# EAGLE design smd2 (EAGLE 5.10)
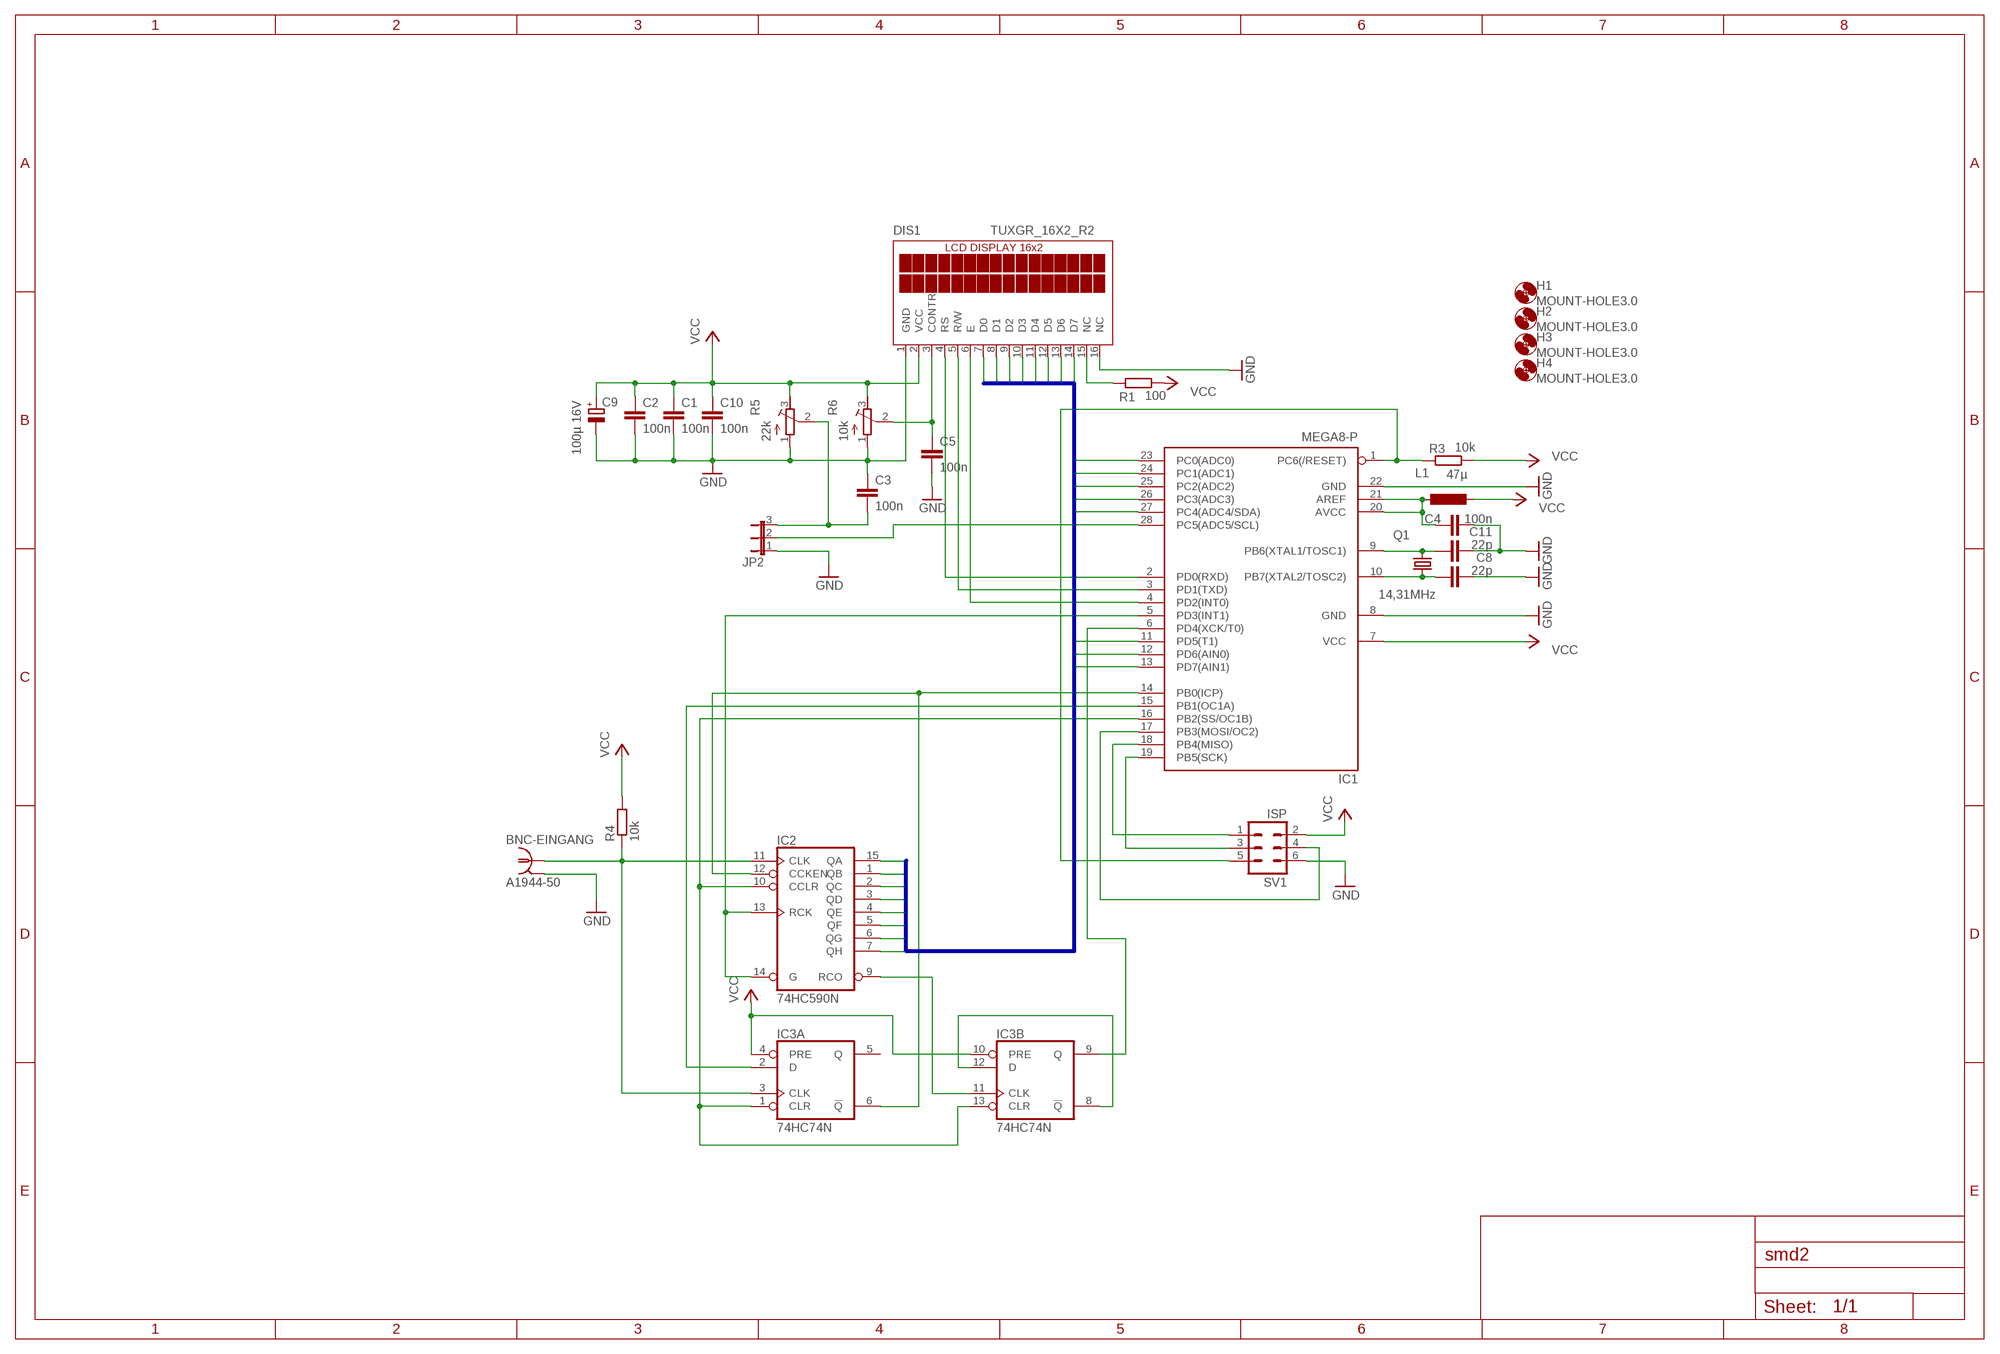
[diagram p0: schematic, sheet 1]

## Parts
BNC-EINGANG  A1944-50  [A1944]
C1  100n  C-EUC1206K  [C1206K]
C2  100n  C-EUC1206K  [C1206K]
C3  100n  C-EUC1206K  [C1206K]
C4  100n  C-EUC1206K  [C1206K]
C5  100n  C-EUC1206K  [C1206K]
C8  22p  C-EUC1206K  [C1206K]
C9  100µ 16V  CPOL-EUE5-8.5  [E5-8,5]
C10  100n  C-EUC1206K  [C1206K]
C11  22p  C-EUC1206K  [C1206K]
DIS1  TUXGR_16X2_R2  [TUXGR_16X2_R2]
H1  MOUNT-HOLE3.0  [3,0]
H2  MOUNT-HOLE3.0  [3,0]
H3  MOUNT-HOLE3.0  [3,0]
H4  MOUNT-HOLE3.0  [3,0]
IC1  MEGA8-P  [DIL28-3]
IC2  74HC590N  [DIL16]
IC3  74HC74N  [DIL14]
JP2  JP2E  [JP2]
L1  47µ  L-EU0204/7  [0204/7]
Q1  14,31MHz  CRYSTALHC49S  [HC49/S]
R1  100  R-EU_0204/7  [0204/7]
R3  10k  R-EU_0204/7  [0204/7]
R4  10k  R-EU_0204/7  [0204/7]
R5  22k  R-TRIMM3296Y  [RTRIM3296Y]
R6  10k  R-TRIMM3296Y  [RTRIM3296Y]
SV1  ISP  ML6  [ML6]

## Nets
0: DIS1.7(D0) IC1.23(PC0(ADC0)) IC2.15(QA)
1: DIS1.8(D1) IC1.24(PC1(ADC1)) IC2.1(QB)
2: DIS1.9(D2) IC1.25(PC2(ADC2)) IC2.2(QC)
3: DIS1.10(D3) IC1.26(PC3(ADC3)) IC2.3(QD)
4: DIS1.11(D4) IC1.27(PC4(ADC4/SDA)) IC2.4(QE)
5: DIS1.12(D5) IC1.11(PD5(T1)) IC2.5(QF)
6: DIS1.13(D6) IC1.12(PD6(AIN0)) IC2.6(QG)
7: DIS1.14(D7) IC1.13(PD7(AIN1)) IC2.7(QH)
GND: BNC-EINGANG.2(GND) C1.2 C2.2 C3.1 C4.2 C5.2 C8.2 C9.- C10.2 C11.2 DIS1.1(GND) DIS1.16(NC) IC1.8(GND) IC1.22(GND) JP2.1 R5.1(E) R6.1(E) SV1.6
N$1: BNC-EINGANG.1 IC2.11(CLK) IC3.3(A:CLK) R4.1
N$2: DIS1.6(E) IC1.4(PD2(INT0))
N$3: DIS1.5(R/W) IC1.3(PD1(TXD))
N$4: DIS1.4(RS) IC1.2(PD0(RXD))
N$5: C5.1 DIS1.3(CONTR) R6.2(S)
N$6: IC1.5(PD3(INT1)) IC2.13(RCK) IC2.14(G)
N$7: IC1.14(PB0(ICP)) IC2.12(CCKEN) IC3.6(A:!Q)
N$8: IC1.16(PB2(SS/OC1B)) IC2.10(CCLR) IC3.1(A:CLR) IC3.13(B:CLR)
N$9: IC2.9(RCO) IC3.11(B:CLK)
N$10: IC1.15(PB1(OC1A)) IC3.2(A:D)
N$11: IC3.8(B:!Q) IC3.12(B:D)
N$12: IC1.6(PD4(XCK/T0)) IC3.9(B:Q)
N$13: IC1.19(PB5(SCK)) SV1.3
N$14: IC1.18(PB4(MISO)) SV1.1
N$15: IC1.17(PB3(MOSI/OC2)) SV1.4
N$16: IC1.1(PC6(/RESET)) R3.1 SV1.5
N$17: C3.2 JP2.3 R5.2(S)
N$18: C4.1 IC1.20(AVCC) IC1.21(AREF) L1.1
N$19: C11.1 IC1.9(PB6(XTAL1/TOSC1)) Q1.2
N$20: C8.1 IC1.10(PB7(XTAL2/TOSC2)) Q1.1
N$21: DIS1.15(NC) R1.1
N$22: IC1.28(PC5(ADC5/SCL)) JP2.2
VCC: C1.1 C2.1 C9.+ C10.1 DIS1.2(VCC) IC1.7(VCC) IC3.4(A:PRE) IC3.10(B:PRE) L1.2 R1.2 R3.2 R4.2 R5.3(A) R6.3(A) SV1.2
Unconnected: IC3.5(A:Q)

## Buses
B$1

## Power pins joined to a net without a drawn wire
GND: BNC-EINGANG.3(GND) BNC-EINGANG.4(GND) BNC-EINGANG.5(GND) IC2.8(GND) IC3.7(P:GND)
VCC: IC2.16(VCC) IC3.14(P:VCC)

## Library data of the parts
BNC-EINGANG = con-coax:A1944-50: BNC CONNECTOR 50 Ohm distributor Buerklin 78F2475
C1-C5 C8 C10 C11 = rcl:C-EU: CAPACITOR, European symbol
C9 = rcl:CPOL-EU: POLARIZED CAPACITOR, European symbol
DIS1 = display-lcd:TUXGR_16X2_R2: Tuxgraphics LCD display 16x2 characters reflective, without background light Source: tuxgr_12x2_r2.pdf
H1-H4 = holes:MOUNT-HOLE: MOUNTING HOLE with drill center marker
IC1 = atmel:MEGA8-P: MICROCONTROLLER 8 Kbytes FLASH, 1 kbytes SRAM, 512 bytes EEPROM, USART, 4-channel 10 bit ADC, 2-channel 8 bit ADC Pin compatible with Atmega48, ATMega88, ATMega168 Source: avr.lbr
IC2 = 74xx-eu:74*590: 8-bit binary COUNTER, output register
IC3 = 74xx-eu:74*74: Dual D type positive edge triggered FLIP FLOP, preset and clear
JP2 = jumper:JP2E: JUMPER
L1 = rcl:L-EU: INDUCTOR, European symbol
Q1 = crystal:CRYSTAL: CRYSTAL
R1 R3 R4 = rcl:R-EU_: RESISTOR, European symbol
R5 R6 = rcl:R-TRIMM: Trimm resistor
SV1 = con-harting-ml:ML6: HARTING

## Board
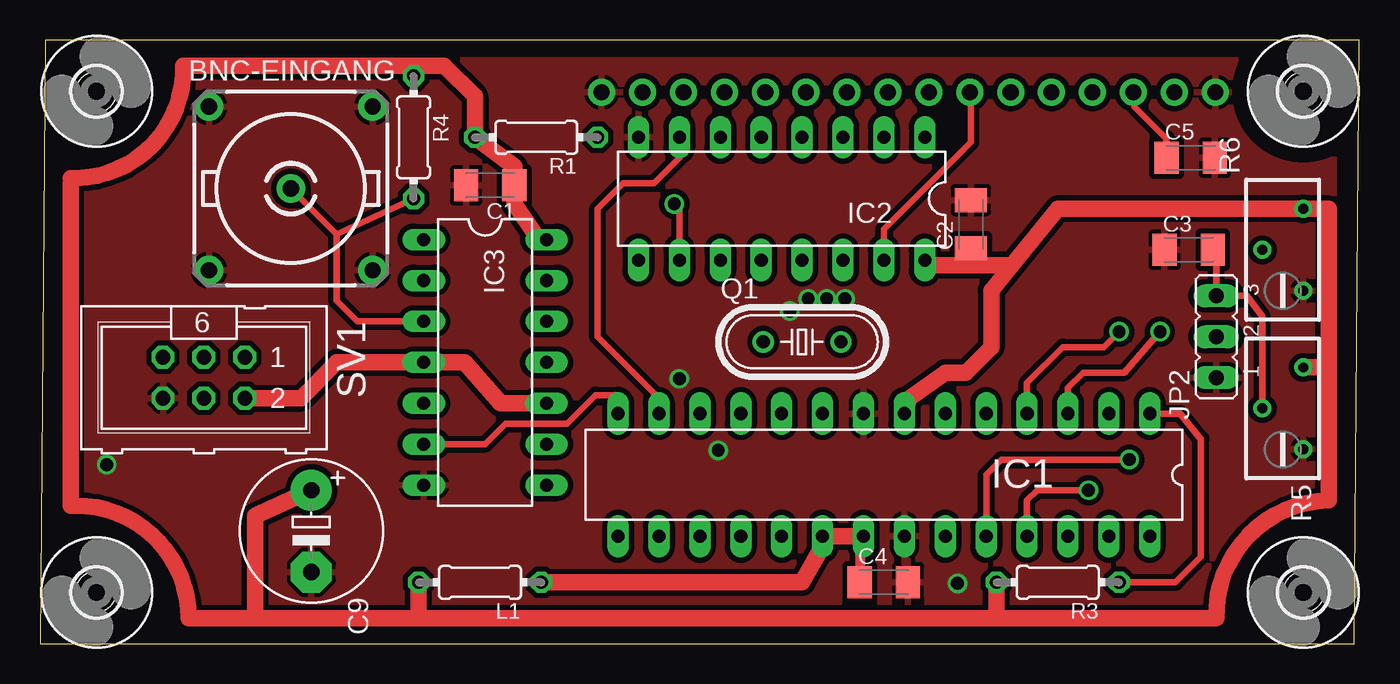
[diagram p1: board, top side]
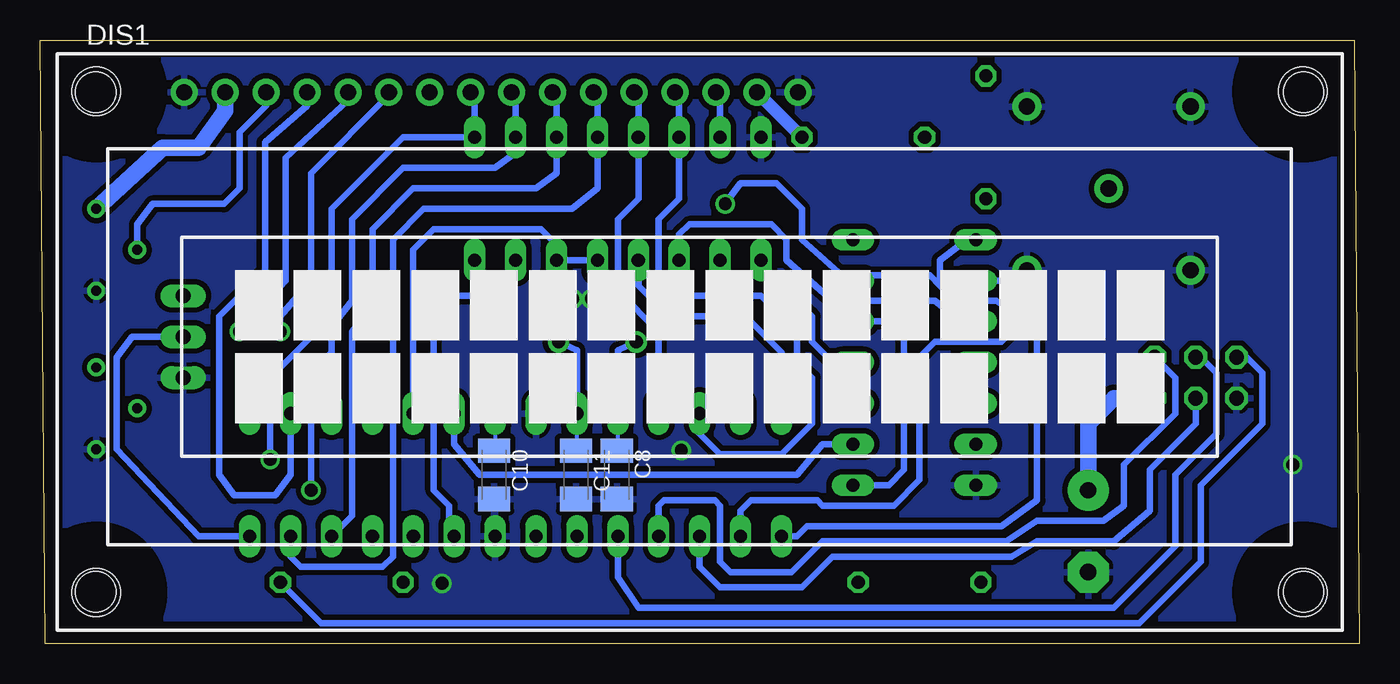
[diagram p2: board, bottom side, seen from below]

Size 81.9 x 37.45 mm. Coordinates in mm from the lower left corner, seen from the top.
Outline: 0,0 81.58,0 81.9,37.46 0.32,37.46 0,0
Copper layers (1*16): Top 0.035mm / dielectric 1.5mm / Bottom 0.035mm
Design rules "Bilex DRU *": minimum track width 10mil, minimum drill 24mil, track to track 10mil, track to pad 10mil, pad to pad 10mil, via to via 10mil, smd to smd 10mil, copper to edge 40mil, drill to drill 8mil, minimum pad ring 10mil, minimum via ring 8mil, stop-mask expansion 4mil, vias tented up to drill 0mil, thermal gap 10mil

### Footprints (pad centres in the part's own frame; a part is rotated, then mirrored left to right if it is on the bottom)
A1944 = drill 1.016 pad 1.778 round: 1 0,0; 2 5.08,5.08; 3 -5.08,5.08; 4 -5.08,-5.08; 5 5.08,-5.08
C1206K = smd 1.5 x 2: 1 -1.5,0; 2 1.5,0
E5-8,5 = drill 1.016 pad 2.54 round: + -2.54,0 | drill 1.016 pad 2.54 octagon: - 2.54,0
TUXGR_16X2_R2 = drill 1 pad 1.676 round: 1 -32,15.5; 2 -29.46,15.5; 3 -26.92,15.5; 4 -24.38,15.5; 5 -21.84,15.5; 6 -19.3,15.5; 7 -16.76,15.5; 8 -14.22,15.5; 9 -11.68,15.5; 10 -9.14,15.5; 11 -6.6,15.5; 12 -4.06,15.5; 13 -1.52,15.5; 14 1.02,15.5; 15 3.56,15.5; 16 6.1,15.5 | hole 2.5: -37.5,-15.5; 37.5,-15.5; -37.5,15.5; 37.5,15.5
3,0 = hole 3: 0,0
DIL28-3 = drill 0.813 long: 1 -16.51,-3.81; 2 -13.97,-3.81; 3 -11.43,-3.81; 4 -8.89,-3.81; 5 -6.35,-3.81; 6 -3.81,-3.81; 7 -1.27,-3.81; 8 1.27,-3.81; 9 3.81,-3.81; 10 6.35,-3.81; 11 8.89,-3.81; 12 11.43,-3.81; 13 13.97,-3.81; 14 16.51,-3.81; 15 16.51,3.81; 16 13.97,3.81; 17 11.43,3.81; 18 8.89,3.81; 19 6.35,3.81; 20 3.81,3.81; 21 1.27,3.81; 22 -1.27,3.81; 23 -3.81,3.81; 24 -6.35,3.81; 25 -8.89,3.81; 26 -11.43,3.81; 27 -13.97,3.81; 28 -16.51,3.81
DIL16 = drill 0.813 long: 1 -8.89,-3.81; 2 -6.35,-3.81; 3 -3.81,-3.81; 4 -1.27,-3.81; 5 1.27,-3.81; 6 3.81,-3.81; 7 6.35,-3.81; 8 8.89,-3.81; 9 8.89,3.81; 10 6.35,3.81; 11 3.81,3.81; 12 1.27,3.81; 13 -1.27,3.81; 14 -3.81,3.81; 15 -6.35,3.81; 16 -8.89,3.81
DIL14 = drill 0.813 long: 1 -7.62,-3.81; 2 -5.08,-3.81; 3 -2.54,-3.81; 4 0,-3.81; 5 2.54,-3.81; 6 5.08,-3.81; 7 7.62,-3.81; 8 7.62,3.81; 9 5.08,3.81; 10 2.54,3.81; 11 0,3.81; 12 -2.54,3.81; 13 -5.08,3.81; 14 -7.62,3.81
JP2 = drill 0.914 long: 1 -2.54,0; 2 0,0; 3 2.54,0
0204/7 = drill 0.813 octagon: 1 -3.81,0; 2 3.81,0
HC49/S = drill 0.813 round: 1 -2.413,0; 2 2.413,0
RTRIM3296Y = drill 0.61 round: 1 1.27,-2.54; 2 -1.27,0; 3 1.27,2.54
ML6 = drill 0.914 octagon: 1 -2.54,-1.27; 2 -2.54,1.27; 3 0,-1.27; 4 0,1.27; 5 2.54,-1.27; 6 2.54,1.27

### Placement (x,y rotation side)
BNC-EINGANG  15.56,28.26 0 top
C1  27.94,28.45 180 top
C2  57.78,26.04 90 top
C3  71.31,24.45 0 top
C4  52.39,3.81 0 top
C5  71.44,30.16 0 top
C8  46.1,10.48 270 bottom
C9  16.83,6.99 270 top
C10  53.72,10.48 270 bottom
C11  48.64,10.48 270 bottom
DIS1  40.96,18.73 0 bottom
H1  3.49,3.18 0 top
H2  3.49,34.29 0 top
H3  78.42,34.29 0 top
H4  78.42,3.18 0 top
IC1  52.39,10.48 180 top
IC2  46.04,27.62 180 top
IC3  27.62,17.46 270 top
JP2  73.02,19.05 90 top
L1  27.31,3.81 180 top
Q1  47.31,18.73 0 top
R1  30.8,31.43 180 top
R3  63.18,3.81 180 top
R4  23.18,31.43 90 top
R5  77.15,14.61 0 top
R6  77.15,24.45 0 top
SV1  10.16,16.51 180 top

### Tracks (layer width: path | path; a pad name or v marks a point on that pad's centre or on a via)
0
  Top 0.406: DIS1.7 57.78,34.17 57.78,31.11 52.39,25.72 IC2.15
  Bottom 0.406: IC1.23 56.52,6.99 56.52,8.57 57.47,9.53 57.47,20.32 56.2,21.59 53.66,21.59 52.39,22.86 IC2.15
1  (via drill 0.8)
  Top 0.406: IC1.24 58.74,10.48 59.69,11.43 v67.63,11.43
  Bottom 0.406: v67.63,11.43 67.63,16.51 65.09,19.05 65.09,20.32 63.82,21.91 63.82,26.99 59.37,31.43 IC2.1 54.93,33.98 DIS1.8
2  (via drill 0.8)
  Top 0.406: IC1.25 61.28,8.89 61.91,9.53 v65.09,9.53
  Bottom 0.406: v65.09,9.53 65.09,16.83 63.82,18.1 63.82,19.68 62.55,21.27 62.55,26.35 59.37,29.53 53.66,29.53 52.39,30.48 IC2.2 52.39,33.98 DIS1.9
3
  Bottom 0.406: IC1.26 62.55,7.94 62.55,19.37 61.28,20.96 61.28,25.72 58.74,28.26 51.12,28.26 49.85,29.21 IC2.3 49.85,33.98 DIS1.10
4
  Bottom 0.406: IC1.27 66.36,5.4 65.72,4.76 60.64,4.76 60.01,5.4 60.01,25.08 58.1,26.99 48.89,26.99 47.31,28.26 IC2.4 47.31,33.98 DIS1.11
5
  Bottom 0.406: IC1.11 43.5,19.37 46.04,21.91 46.04,26.35 44.77,27.62 IC2.5 44.77,33.98 DIS1.12
6
  Bottom 0.406: IC1.12 40.96,13.02 39.69,11.75 35.88,11.75 33.97,13.65 33.97,16.51 34.93,17.46 34.93,19.37 37.15,21.59 42.54,21.59 43.5,22.54 43.5,26.35 42.23,27.62 IC2.6 42.23,33.98 DIS1.13
7
  Top 0.406: IC1.13 38.42,15.24 34.61,19.05 34.61,26.99 36.2,28.57 38.1,28.57 39.69,30.16 IC2.7
  Bottom 0.406: IC2.7 39.69,33.98 DIS1.14
GND  (via drill 0.8 pad 0.9)
  other vias: 4.13,11.11 46.55,20.64 47.69,21.4 48.83,21.4 49.97,21.4 56.96,3.75 42.1,12 39.69,16.45
  pour Top (isolate 0.33): 1.59,1.59 80.33,1.59 80.33,36.51 1.59,36.51
  pour Bottom (isolate 0.33): 1.59,1.59 80.33,1.59 80.33,36.51 1.59,36.51
N$1
  Top 0.406: 18.41,25.4 BNC-EINGANG.1 | 18.41,25.4 R4.1 | IC3.3 19.69,20 18.41,21.27 18.41,25.4
  Bottom 0.254: IC3.3 24.76,20
  Bottom 0.406: 24.76,20 26.35,21.27 32.7,21.27 35.56,23.81 35.56,25.08 36.51,26.03 41.59,26.03 42.23,25.4 IC2.11
N$2  (via drill 0.8)
  Top 0.406: IC1.4 61.28,16.19 63.5,18.42 66.04,18.42 v66.99,19.37
  Bottom 0.406: DIS1.6 60.26,34.04 65.09,29.21 65.09,22.54 66.99,20.32 v66.99,19.37
N$3  (via drill 0.8)
  Top 0.406: IC1.3 63.82,15.88 64.77,16.83 67.31,16.83 v69.53,19.37
  Bottom 0.406: DIS1.5 62.8,33.72 66.68,30.16 66.68,22.54 v69.53,19.37
N$4
  Bottom 0.406: DIS1.4 65.34,33.4 67.94,31.11 67.94,23.18 70.8,20.32 70.8,10.48 69.85,9.21 67.31,9.21 66.36,10.48 IC1.2
N$5
  Top 0.406: C5.1 69.94,31.35 67.94,33.34 67.94,34.17 DIS1.3
  Bottom 0.406: DIS1.3 67.88,33.4 69.53,31.75 69.53,28.26 70.49,27.31 74.93,27.31 75.88,26.03 R6.2
N$6
  Bottom 0.406: IC2.13 IC2.14 49.85,24.76 50.8,25.72 57.47,25.72 58.74,24.45 IC1.5
N$7
  Top 0.406: IC1.14 35.88,15.43 34.48,15.43 32.7,13.65 28.89,13.65 27.62,12.38 IC3.6
  Bottom 0.406: IC1.14 35.88,18.1 38.1,20.32 42.86,20.32 44.77,22.22 IC2.12
N$8  (via drill 0.8)
  Top 0.406: v39.37,27.31 39.69,26.99 IC2.10
  Bottom 0.406: v39.37,27.31 38.42,28.57 36.2,28.57 34.61,26.99 34.61,25.08 31.75,22.54 IC3.13 31.11,22.86 26.67,22.86 26.03,22.22 | IC1.16 38.42,8.25 37.78,8.89 33.65,8.89 33.34,8.57 28.89,8.57 27.31,10.16 27.31,17.78 26.35,18.73 22.23,18.73 21.59,19.37 21.59,20.64 22.54,21.27 25.08,21.27 26.03,22.22 | 26.03,22.22 26.03,23.81 24.76,24.76 24.13,24.76 IC3.1
N$9
  Bottom 0.406: IC3.11 32.7,17.46 33.97,18.73 33.97,20.32 37.15,23.18 IC2.9
N$10
  Bottom 0.406: IC1.15 34.93,6.67 34.29,7.3 22.23,7.3 20,8.89 20,20.64 22.23,22.54 IC3.2
N$11
  Bottom 0.406: IC3.12 29.21,20 28.26,19.05 28.26,10.79 29.21,9.84 IC3.8
N$12
  Bottom 0.406: IC1.6 56.2,12.38 54.61,10.48 34.93,10.48 33.34,12.38 IC3.9
N$13
  Bottom 0.406: IC1.19 46.04,4.13 44.77,2.22 15.24,2.22 11.43,6.03 11.43,10.48 8.89,13.02 8.89,16.83 9.84,17.78 SV1.3
N$14
  Bottom 0.406: IC1.18 43.5,8.57 43.18,8.89 40,8.89 39.69,8.57 39.69,5.08 39.05,4.44 35.24,4.44 33.34,6.35 21.91,6.35 20,7.62 15.87,7.62 14.6,8.57 14.6,11.11 11.43,14.29 11.43,16.51 SV1.1
N$15
  Bottom 0.406: IC1.17 40.96,4.76 39.69,3.49 34.61,3.49 32.7,5.4 21.59,5.4 20,6.35 15.24,6.35 13.02,8.25 13.02,10.79 10.16,13.65 SV1.4
N$16
  Top 0.406: IC1.1 70.8,14.29 72.07,12.7 72.07,5.4 70.49,3.81 R3.1
  Bottom 0.406: R3.1 64.45,1.27 13.65,1.27 9.84,5.08 9.84,9.84 6.03,13.65 6.03,16.83 6.99,17.78 SV1.5
N$17
  Top 0.254: C3.2 72.71,24.57 72.77,24.45
  Top 0.406: R5.2 75.88,20.32 74.93,21.59 JP2.3 73.02,23.81 72.77,24.45
N$18
  Top 0.61: 50.89,6.44 C4.1
  Top 1.016: L1.1 47.31,3.81 48.58,6.03 IC1.20 IC1.21 50.89,6.44
N$19
  Bottom 0.254: C11.1 48.58,12.13 IC1.9
  Bottom 0.406: IC1.9 48.58,18.22 Q1.2
N$20
  Bottom 0.254: C8.1 46.04,12.13 IC1.10
  Bottom 0.406: IC1.10 46.04,18.22 Q1.1
N$21
  Bottom 0.813: R1.1 DIS1.15
N$22
  Bottom 0.406: JP2.2 76.2,19.05 77.15,17.78 77.15,12.07 72.07,6.67 IC1.28
VCC
  Top 0.254: C1.1 29.53,28.64 29.44,28.64 | 1.91,28.57 2.1,28.89
  Top 0.406: 57.78,23.5 C2.1
  Top 1.016: 23.5,1.59 L1.2 | 23.5,1.59 59.37,1.59 | 59.37,1.59 73.02,1.59 arc-90 80.01,8.89 80.01,17.14 | 80.01,17.14 R5.3 | 80.01,17.14 80.01,26.99 R6.3 63.18,26.99 60.33,23.5 | IC3.10 28.57,14.92 26.35,17.46 IC3.4 18.41,17.46 16.19,15.24 SV1.2 | 13.34,1.59 9.21,1.59 arc90 2.22,8.57 1.91,8.57 1.91,28.57 | 13.34,1.59 23.5,1.59 | IC1.7 53.97,15.24 56.2,16.83 57.47,16.83 59.06,18.42 59.06,21.91 60.33,23.5 | 60.33,23.5 57.78,23.5 55.25,23.5 IC2.16 | IC3.14 30.71,25 30.71,25.4 29.44,27.31 C1.1 29.44,28.64 29.44,29.61 R1.2 26.99,33.97 25.08,35.88 23.18,35.88 | 23.18,35.88 8.89,35.88 arc-90 2.22,28.89 2.1,28.89 1.91,28.89 | 59.37,1.59 R3.2 | 23.18,35.88 R4.2 | 13.34,1.59 13.34,7.94 C9.+
  Bottom 0.254: C10.1 53.66,12.13 IC1.7
  Bottom 1.016: DIS1.2 70.42,33.09 72.07,30.8 74.3,30.8 R6.3 | C9.+ 16.83,13.65 15.24,15.24 SV1.2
